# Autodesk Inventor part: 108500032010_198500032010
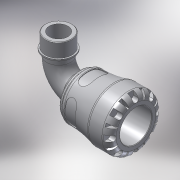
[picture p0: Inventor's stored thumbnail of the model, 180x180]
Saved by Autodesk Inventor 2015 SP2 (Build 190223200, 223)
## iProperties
Created: 2016-12
Part Number: 108500032010_198500032010
Material: PVC-Piping
Description: PLASSON 90° ELBOW WITH THREADED MALE OFFTAKE 32X1" SERIES 1
Document SubType Name: Modeling
Designer: KIM
Mass: 145.018 g
Surface Area: 316.161 cm^2
Volume: 103.584 cm^3
Density: 1.4 g/cm^3
Appearance: Smooth - White
Author: KIM
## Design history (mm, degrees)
derived "1085.ipt"
feature "Solid1::1085.ipt"
tag "TaggingFeature1"
body "Solid1"
other parameters: "d1" = 22.26, "d2" = 32, "d4" = 58, "d8" = 49.3, "d13" = 7.2, "d14" = 7.2, "d15" = 0, "d17" = 360 deg, "d19" = 8 deg, "d20" = 0.64, "d21" = 0.64, "d22" = 8 deg, "d24" = 0, "d26" = 360 deg, "d33" = 5.8, "d43" = 45.24, "d51" = 0.58, "d54" = 11.2, "d55" = 7.04, "d57" = 14.112, "d58" = 0, "d74" = 0, "d78" = 53, "d82" = 0.64, "d115" = 360 deg, "d207" = 90 deg, "d228" = 9.52, "d247" = 1.16, "d248" = 3.18, "d268" = 27.115, "d269" = 3.18, "d270" = 81, "d276" = 33.249, "d277" = 19, "d278" = 36.5739, "d279" = 53, "d280" = 20.9, "d281" = 4.98735, "d283" = 29.9241, "d286" = 0, "d287" = 0, "d288" = 23.2743, "d290" = 7.65795, "d292" = 30 deg, "d_" = 32, "E_" = 58, "l_" = 53, "A_" = 81, "A_1" = 53, "l_2" = 19, "R_" = 33.249, "d9" = 9, "d11" = 58, "d289" = 23.2743
